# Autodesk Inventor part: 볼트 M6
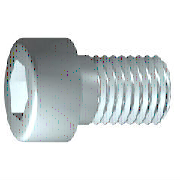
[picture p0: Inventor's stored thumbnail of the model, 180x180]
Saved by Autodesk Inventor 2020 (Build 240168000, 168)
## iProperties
IsCustomPart: 1
Created: 2012-02
Part Number: 볼트 M6
Material: 강철, 연강
Document SubType Name: Modeling
Standard: JIS B 1176
Designer: mdu-01
Standards Organization: JIS
Language: ko-KR
Size Designation: M6 x 16
Categories: <MemberInstance><Categories><Category DisplayName="조임쇠" InternalName="e4da775c-781d-43d5-af7c-5136215cf5a6" Mnemonic="FSTN"><Category DisplayName="볼트" InternalN
Density: 1 g/cm^3
Appearance: 강철
Author: mdu-01
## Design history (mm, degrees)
sketch "스케치1"
  geometry: L1 (-1.333, 0)-(16, 0); L2 (16, 0)-(16, 3); L3 (16, 3)-(2.5, 3); L4 (2.5, 3)-(1.886, 3); L5 (1.886, 3)-(0, 3); L6 (0, 3)-(0, 5); L7 (0, 5)-(-6, 5); L8 (-6, 5)-(-6, 2.887); L9 (-6, 2.887)-(-3, 2.887); L10 (-3, 2.887)-(-1.333, 0); L11 (-10.4, 0)-(20.4, 0) reference; L12 (0, -1)-(0, 6) reference; L13 (2.5, 3)-(0, 3)
  constraints: 22 end point, 6 parallel, 2 collinear, 2 perpendicular, 1 horizontal, 1 point on line
  dimensions: "d1" = 13.5 distance from line of L3.end L2 (= GEL); "d2" = 0.61355 distance of L4.end L3.end (computed from GAL); "d3" = 6 distance between parallel lines of L8 L6 (= KOH); "d4" = 3 distance of L8.end L9.end (= INTI); "d5" = 60 deg angle of L10 L1; "d6" = 6 diameter of L3 L1 (= GD); "d7" = 6 diameter of L5 L1 (= BDM); "d8" = 5.7735 diameter of L9 L1 (= 1.1547 x SW); "d9" = 10 diameter of L7 L1 (= KOD); "d26" = 16 distance between parallel lines of L12 L2 (= NLG)
revolve "본체" sketch "스케치1" stored, may be unused: angle "d10" = 90 deg
sketch "스케치2"
  geometry: L1 (0, -7)-(0, 7) reference; L2 (-7, 0)-(7, 0) reference; L3 (2.887, 0)-(1.443, -2.5); L4 (1.443, -2.5)-(-1.443, -2.5); L5 (-1.443, -2.5)-(-2.887, 0); L6 (-2.887, 0)-(-1.443, 2.5); L7 (-1.443, 2.5)-(1.443, 2.5); L8 (1.443, 2.5)-(2.887, 0); 2 further points
  constraints: 12 end point, 1 coincident, 1 horizontal alignment, 1 point on line, 12 other
extrude "슬롯" join sketch "스케치2" stored distance "d11" = 10; taper "d12" = 0 deg
workplane "Work Plane1"
fillet "Fillet2" dims "d30" = 0.1 (= R)
body "Solid1"
fillet "모깎기1" dims "d17" = 0.6 (= RR)
feature "스레드" dims "d13" = 13.5 (= GEL), "d14" = 0
chamfer "모따기1" distance "d15" = 0.61345 (= -0.5 x SPD + 0.5 x GD); stored, may be unused: second distance "d16" = 0.61345 (= GUL), angle "d27" = 45 deg
other parameters: "GD" = 6 (= NND) [user parameter; used in 2 equation terms], "NLG" = 16 [user parameter; used in 1 equation term], "GEL" = 13.5 [user parameter; used in 2 equation terms], "KOD" = 10 [user parameter; used in 1 equation term], "KOH" = 6 [user parameter; used in 1 equation term], "INTI" = 3 [user parameter; used in 1 equation term], "GAL" = 0.61345 (= 0.61345 x PTC) [user parameter; used in 1 equation term], "GUL" = 0.61345 (= 0.61345 x PTC) [user parameter; used in 1 equation term], "BDM" = 6 (= NND) [user parameter; used in 1 equation term], "SW" = 5 [user parameter; used in 2 equation terms], "RR" = 0.6 [user parameter; used in 1 equation term], "SPD" = 4.7731 (= NND - 1.2269 x PTC) [user parameter; used in 1 equation term], "d19" = 0, "d28" = 0, "d29" = 0, "R" = 0.1 [user parameter; used in 1 equation term], "PHH" = 0.25 [user parameter], "GD1" = 4.7731 (= THREADDIA - 1.2269 x PTC) [user parameter], "THREADDIA" = 6 [user parameter; used in 1 equation term], "FAWI" = 45 deg [user parameter], "PTC" = 1 [user parameter; used in 5 equation terms], "NND" = 6 [user parameter; used in 3 equation terms], "TOA" = 30 deg [user parameter], "E0" = 5.775 (= 1.155 x SW) [user parameter]
